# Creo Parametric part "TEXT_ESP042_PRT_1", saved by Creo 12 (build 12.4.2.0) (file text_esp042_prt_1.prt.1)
Units: Custom; MM, KILOGRAM, SECS

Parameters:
  PTC_WM_ITERATION = "0"
  PTC_WM_VERSION = "-.0"
  PTC_WM_LIFECYCLE_STATE = "In Work"
  PTC_WM_LIFECYCLE = "MO_CADDocument"
  PTC_WM_CREATED_BY = "Maximilian Roepper (Z0017RMS: MO)"
  PTC_WM_CREATED_ON = "18-Sep-26 11:36:42 AM"
  PTC_WM_MODIFIED_BY = "Maximilian Roepper (Z0017RMS: MO)"
  PTC_WM_MODIFIED_ON = "18-Sep-26 11:36:46 AM"
  PDMLINKNUMBER = "PDM000071454982"
  PTC_WM_NAME = "text_esp042_prt_1.prt"
  PTC_WM_NUMBER = "PDM000071454982"

Other parameters: WEIGHT, WEIGHT_FACTOR, WEIGHT_ADD, _MASS_TEMP, _DIFF_TEMP, MC_ERRORS, SUPPLIER

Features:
  1. coordinate system
  2. datum plane "PRT_YZ"
  3. datum plane "PRT_XY"
  4. datum plane "PRT_XZ"
  5. coordinate system
  6. datum axis
  7. datum axis
  8. datum axis
  9. coordinate system
  10. imported feature
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
Other named items: PRT, SIEMENS_MO, DRW_VIEW_ORG, PRT_X, PRT_Y, PRT_Z, CS0, ROUGH_GROB

Layers: 00_STD_CSYS-KSYS, 01_STD_PLANES-EBENEN, 02_STD_AXES-ACHSEN, 03_STD_CSYS-KSYS, 24_IMPORT_FEAT-IMPORT_KE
